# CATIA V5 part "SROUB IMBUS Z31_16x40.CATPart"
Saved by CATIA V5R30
Part number: SROUB IMBUS Z31/16x40
Bounding box of the stored display mesh (mm): x -16 to 40, y -11.99 to 11.99, z -12 to 12
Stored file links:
  C:\Users\ondra\Desktop\PŘÍLOHA P III\CATIA\SROUB IMBUS Z31_16x40.CATPart
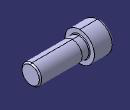
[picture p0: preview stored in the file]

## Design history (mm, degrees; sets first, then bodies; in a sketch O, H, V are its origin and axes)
Set1
  DatumSurface1 to DatumSurface30 "Z31/16x4"
  Join1: Elements (DatumSurface1; DatumSurface2; DatumSurface3; DatumSurface4; DatumSurface5; DatumSurface6; DatumSurface7; DatumSurface8; DatumSurface9; DatumSurface10; DatumSurface11; DatumSurface12; DatumSurface13; DatumSurface14; DatumSurface16; DatumSurface17; DatumSurface18; DatumSurface19; DatumSurface20; DatumSurface21; DatumSurface22; DatumSurface23; DatumSurface24; DatumSurface25; DatumSurface26; DatumSurface27; DatumSurface28; DatumSurface29; DatumSurface30)
Body1 (main body)
  CloseSurface1: CloseElement Join1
